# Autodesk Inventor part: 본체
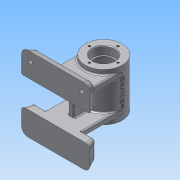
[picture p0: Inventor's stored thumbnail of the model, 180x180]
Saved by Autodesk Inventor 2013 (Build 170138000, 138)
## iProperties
Created: 2016-07
Part Number: 본체
Material: 알루미늄 6061
Document SubType Name: Modeling
Designer: Administrator
Density: 2.71 g/cm^3
Mass: 504.06 g
Surface Area: 540.608 cm^2
Volume: 186 cm^3
Author: Administrator
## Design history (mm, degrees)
sketch "스케치1"
  geometry: C1 r 27 at (0, 0); 1 further point
  constraints: 1 centre point, 1 coincident
  dimensions: "d0" = 54 diameter of C1
extrude "돌출1" new body sketch "스케치1" distance "d1" = 35; taper "d2" = 0 deg
sketch "스케치2"
  geometry: C1 r 27 at (0, 0) reference; C2 r 16 at (0, 0)
  constraints: 1 centre point, 1 coincident
  dimensions: "d3" = 32 diameter of C2
extrude "돌출2" cut sketch "스케치2" distance "d4" = 12; taper "d5" = 0 deg
chamfer "모따기1" distance "d6" = 1; stored, may be unused: second distance "d7" = 2, angle "d8" = 45 deg
fillet "모깎기1" dims "d9" = 0.3
sketch "스케치3"
  geometry: C1 r 15.7 at (0, 0) reference; C2 r 14 at (0, 0)
  constraints: 1 centre point, 1 coincident
  dimensions: "d10" = 28 diameter of C2
extrude "돌출3" cut sketch "스케치3" distance "d11" = 2; taper "d12" = 0 deg
sketch "스케치4"
  geometry: C1 r 27 at (0, 0) reference; C2 r 22 at (0, 0)
  constraints: 1 centre point, 1 coincident
  dimensions: "d13" = 44 diameter of C2
extrude "돌출4" cut sketch "스케치4" distance "d14" = 21; taper "d15" = 0 deg
fillet "모깎기2" dims "d16" = 3
sketch "스케치5"
  geometry: C1 r 27 at (0, 0) reference; 1 further point
  constraints: 1 vertical alignment
  dimensions: "d17" = 21 distance of C1.centre point (0, 21)
hole "구멍1" sketch "스케치5" at (0, 21) diameter "d18" = 3.242; stored, may be unused: countersink angle "d22" = 90 deg, drill point angle "d24" = 118 deg; dims "d19" = 8, "d20" = 4, "d21" = 2, "d23" = 10
node "작업 평면1"
sketch "스케치6"
  geometry: L1 (27, 35)-(-27, 35) reference; C1 r 5 at (0, 13); 2 further points
  constraints: 1 centre point, 1 midpoint, 1 vertical alignment
  dimensions: "d29" = 10 diameter of C1; "d30" = 22 distance from line of C1.centre L1
extrude "돌출5" join sketch "스케치6" stored distance "d31" = 21; taper "d32" = 0 deg
fillet "모깎기3" dims "d33" = 2
sketch "스케치7"
  geometry: C1 r 5 at (0, 0) reference; 2 further points
  constraints: 1 coincident
hole "구멍2" sketch "스케치7" at (0, 0) diameter "d34" = 5.188; stored, may be unused: countersink angle "d38" = 90 deg, drill point angle "d40" = 118 deg; dims "d35" = 8, "d36" = 4, "d37" = 2, "d39" = 10
node "작업 평면2"
sketch "스케치8"
  geometry: L1 (50, 20)-(-50, 20); L2 (-50, 20)-(-50, 55); L3 (-50, 55)-(50, 55); L4 (50, 55)-(50, 20); L5 (50, 20)-(-50, 55); L6 (-50, 20)-(50, 55); 3 further points
  constraints: 12 end point, 3 midpoint, 2 parallel, 1 horizontal, 1 perpendicular, 1 vertical alignment
  dimensions: "d42" = 100 distance of L2.end L3.end; "d43" = 35 distance of L1.end L2.end; "d44" = 55 vertical distance of L2.end point (0, 0)
extrude "돌출6" join sketch "스케치8" distance "d45" = 12; taper "d46" = 0 deg
sketch "스케치12"
  geometry: L1 (50, -20)-(-50, -20) reference; L2 (-50, -55)-(-50, -20) reference; L3 (-50, -20)-(50, -20) reference; L4 (50, -20)-(50, -55) reference; L5 (-27, -20)-(27, -20); L6 (27, -20)-(27, -28); L7 (27, -28)-(-27, -28); L8 (-27, -28)-(-27, -20); L9 (-27, -20)-(27, -28); L10 (27, -20)-(-27, -28); L11 (50, -55)-(-50, -55) reference; 3 further points
  constraints: 12 end point, 4 midpoint, 2 parallel, 1 horizontal, 1 perpendicular
  dimensions: "d65" = 54 distance of L6.end L7.end; "d66" = 8 distance of L5.end L6.end
extrude "돌출8" join sketch "스케치12" stored distance "d67" = 12; taper "d68" = 0 deg
fillet "모깎기6" dims "d69" = 2
fillet "모깎기9" dims "d72" = 2
node "작업 평면3"
sketch "스케치19"
  geometry: L1 (-57.621, 20)-(-70, 20) reference; L2 (-70, 20)-(-70, 55) reference; L3 (-58, 55)-(-58, 29.464) reference; L4 (-56, 26)-(-56, 22) reference; L5 (-56, 26)-(0, 26) reference; L6 (0, 26)-(0, 35) reference; L7 (-56, 22)-(0, 22) reference; L8 (0, -35)-(0, 22) reference; L9 (0, 22)-(0, 26) reference; L10 (27, 35)-(-27, 35) reference; L11 (-70, 55)-(-58, 55) reference; 2 further points
  constraints: 1 coincident, 3 other
  dimensions: "d130" = 35 distance from line of L10 point (0, 0); "d188" = 27 horizontal distance of L10.start point (0, 0) (derived)
feature "엠보싱1" sketch "스케치19" dims "d131" = 0.5, "d132" = 0
node "작업 평면4"
sketch "스케치21"
  geometry: C1 r 6 at (0, 0); 1 further point
  constraints: 1 centre point, 1 coincident
  dimensions: "d136" = 12 diameter of C1
extrude "돌출11" join sketch "스케치21" stored distance "d137" = 12; taper "d138" = 0 deg
fillet "모깎기18" dims "d139" = 2
sketch "스케치22"
  geometry: C1 r 6 at (0, 0) reference; 1 further point
  constraints: 1 coincident
hole "구멍6" sketch "스케치22" at (0, 0) diameter "d140" = 5.134; stored, may be unused: countersink angle "d144" = 90 deg, drill point angle "d146" = 0 deg; dims "d141" = 6, "d142" = 10, "d143" = 4, "d145" = 10
fillet "모깎기23" dims "d171" = 2
sketch "스케치26"
  geometry: L1 (16, 23.3)-(16, 34) reference; L2 (16, 34)-(17, 35) reference; L3 (17, 35)-(19.379, 35) reference; L4 (19.379, 35)-(19.379, 25) reference; L5 (19.379, 25)-(21, 24.026) reference; L6 (21, 24.026)-(22.621, 25) reference; L7 (22.621, 25)-(22.621, 35) reference; L8 (22.621, 35)-(27, 35) reference; L9 (27, 35)-(27, 20) reference; L10 (29, 18)-(30, 18) reference; L11 (30, 18)-(30, 15.594) reference; L12 (30, 15.594)-(22, 15.594) reference; L13 (22, 15.594)-(22, 18) reference; L14 (19, 21)-(14, 21) reference; L15 (14, 21)-(14, 23) reference; L16 (14, 23)-(15.7, 23) reference; L17 (15.7, -23)-(14, -23) reference; L18 (14, -23)-(14, -21) reference; L19 (14, -21)-(19, -21) reference; L20 (22, -18)-(22, 10.406) reference; L21 (22, 10.406)-(30, 10.406) reference; L22 (30, 10.406)-(30, 8) reference; L23 (30, 8)-(29, 8) reference; L24 (27, 6)-(27, -35) reference; L25 (27, -35)-(22.621, -35) reference; L26 (22.621, -35)-(22.621, -25) reference; L27 (22.621, -25)-(21, -24.026) reference; L28 (21, -24.026)-(19.379, -25) reference; L29 (19.379, -25)-(19.379, -35) reference; L30 (19.379, -35)-(17, -35) reference; L31 (17, -35)-(16, -34) reference; L32 (16, -34)-(16, -23.3) reference; L33 (-16, -23.3)-(-16, -34) reference; L34 (-16, -34)-(-17, -35) reference; L35 (-17, -35)-(-19.379, -35) reference; L36 (-19.379, -35)-(-19.379, -25) reference; L37 (-19.379, -25)-(-21, -24.026) reference; L38 (-21, -24.026)-(-22.621, -25) reference; L39 (-22.621, -25)-(-22.621, -35) reference; L40 (-22.621, -35)-(-27, -35) reference; L41 (-27, -35)-(-27, -28) reference; L42 (-58, -55)-(-70, -55) reference; L43 (-70, -55)-(-70, -20) reference; L44 (-70, -20)-(-27, -20) reference; L45 (-27, -20)-(-27, 18) reference; L46 (-29, 20)-(-70, 20) reference; L47 (-70, 20)-(-70, 55) reference; L48 (-70, 55)-(-58, 55) reference; L49 (-58, 55)-(-58, 30) reference; L50 (-56, 28)-(-29, 28) reference; L51 (-27, 30)-(-27, 35) reference; L52 (-27, 35)-(-22.621, 35) reference; L53 (-22.621, 35)-(-22.621, 25) reference; L54 (-22.621, 25)-(-21, 24.026) reference; L55 (-21, 24.026)-(-19.379, 25) reference; L56 (-19.379, 25)-(-19.379, 35) reference; L57 (-19.379, 35)-(-17, 35) reference; L58 (-17, 35)-(-16, 34) reference; L59 (-16, 34)-(-16, 23.3) reference; L60 (-15.7, 23)-(-14, 23) reference; L61 (-14, 23)-(-14, 21) reference; L62 (-14, 21)-(-19, 21) reference; L63 (-22, 18)-(-22, -18) reference; L64 (-19, -21)-(-14, -21) reference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; A1 r 3 centre (19, 18) between (22, 18) and (19, 21) reference; A2 r 0.3 centre (15.7, 23.3) between (15.7, 23) and (16, 23.3) reference; A3 r 0.3 centre (15.7, -23.3) between (16, -23.3) and (15.7, -23) reference; A4 r 3 centre (19, -18) between (19, -21) and (22, -18) reference; A5 r 0.3 centre (-15.7, -23.3) between (-15.7, -23) and (-16, -23.3) reference; A6 r 2 centre (-29, 18) between (-27, 18) and (-29, 20) reference; A7 r 2 centre (-56, 30) between (-58, 30) and (-56, 28) reference; A8 r 2 centre (-29, 30) between (-29, 28) and (-27, 30) reference; A9 r 0.3 centre (-15.7, 23.3) between (-16, 23.3) and (-15.7, 23) reference; A10 r 3 centre (-19, 18) between (-19, 21) and (-22, 18) reference; A11 r 3 centre (-19, -18) between (-22, -18) and (-19, -21) reference; 1 further point
  constraints: 2 end point, 1 perpendicular, 2 other
  dimensions: "d173" = 21 horizontal distance of L67.start L51.end
feature "리브3" sketch "스케치26" dims "d174" = 1, "d175" = 8, "d176" = 0, "d177" = 0, "d178" = 1, "d179" = 1
fillet "모깎기25" dims "d187" = 2
fillet "모깎기27" dims "d190" = 2
sketch "스케치32"
  geometry: L1 (35, 0)-(0, 0) reference; L2 (35, 10)-(35, 0) reference; L3 (35, 0)-(0, 0) reference; L4 (0, 0)-(0, 12) reference; L5 (0, 12)-(33, 12) reference; L6 (75, 0)-(75, 12) reference; L7 (75, 12)-(110, 12) reference; L8 (110, 12)-(110, 0) reference; L9 (110, 0)-(75, 0) reference; L10 (35, 10)-(35, 0) reference; L11 (35, 0)-(0, 0) reference; L12 (0, 0)-(0, 12) reference; L13 (0, 12)-(33, 12) reference; L14 (75, 0)-(75, 12) reference; L15 (75, 12)-(110, 12) reference; L16 (110, 12)-(110, 0) reference; L17 (110, 0)-(75, 0) reference; L18 (110, 0)-(105.632, 12); L19 (0, 0)-(4.368, 12); A1 r 2 centre (33, 10) between (35, 10) and (33, 12) reference; A2 r 2 centre (33, 10) between (35, 10) and (33, 12) reference; 1 further point
  constraints: 4 end point, 2 point on line
  dimensions: "d212" = 110 deg angle of L9 L18; "d214" = 110 deg angle of L1 L19
extrude "돌출16" cut sketch "스케치32" stored distance "d215" = 40; taper "d216" = 0 deg
node "작업 평면5"
sketch "스케치33"
  geometry: L1 (-100, 0)-(-100, 12) reference; L2 (0, 12)-(0, 0) reference; L3 (0, 0)-(-4.368, 12); L4 (-100, 0)-(0, 0) reference; L5 (-100, 12)-(0, 12) reference; L6 (-100, 0)-(-95.632, 12); 1 further point
  constraints: 4 end point, 2 point on line
  dimensions: "d219" = 110 deg angle of L4 L3; "d221" = 110 deg angle of L4 L6
extrude "돌출17" cut sketch "스케치33" distance "d222" = 40; taper "d223" = 0 deg
fillet "모깎기28" dims "d224" = 10
fillet "모깎기29" dims "d225" = 5
fillet "모깎기30" dims "d226" = 2
node "작업 평면6"
sketch "스케치34"
  geometry: L1 (-100, 12)-(0, 12) reference; L2 (0, 0)-(-100, 0) reference; L3 (-100, 0)-(-95.632, 12); L4 (0, 0)-(-4.368, 12); L5 (-100, 0)-(-100, 12) reference; L6 (0, 12)-(0, 0) reference; 1 further point
  constraints: 4 end point, 2 point on line
  dimensions: "d228" = 110 deg angle of L2 L4; "d229" = 110 deg angle of L2 L3
extrude "돌출18" cut sketch "스케치34" distance "d230" = 40; taper "d231" = 0 deg
sketch "스케치35"
  geometry: L1 (-21.83, -52)-(-21.83, -72.433) reference; L2 (-0.536, -50)-(50.536, -50) reference; L3 (67.131, -52)-(54, -52) reference; L4 (67.131, -72.433)-(67.131, -52) reference; L5 (-12.433, -77.131)-(62.433, -77.131) reference; L6 (-17.131, -52)-(-17.131, -72.433) reference; L7 (-4, -52)-(-17.131, -52) reference; L8 (-4, -52)-(-4, -56) reference; L9 (0, -60)-(50, -60) reference; L10 (54, -56)-(54, -52) reference; L11 (-4, -8)-(-4, -4) reference; L12 (0, 0)-(50, 0) reference; L13 (54, -4)-(54, -8) reference; L14 (50, -10)-(0, -10) reference; L15 (-20.632, -8)-(-4, -8) reference; L16 (-20.632, -8)-(-20.632, 20.632) reference; L17 (-20.632, 20.632)-(70.632, 20.632) reference; L18 (70.632, 20.632)-(70.632, -8) reference; L19 (54, -8)-(70.632, -8) reference; L20 (75, -75.603)-(75, -52) reference; L21 (-25, -52)-(-25, -75.603) reference; L22 (-15.603, -85)-(65.603, -85) reference; A1 r 4 centre (0, -56) between (-4, -56) and (0, -60) reference; A2 r 4 centre (50, -56) between (50, -60) and (54, -56) reference; A3 r 4 centre (0, -4) between (0, 0) and (-4, -4) reference; A4 r 4 centre (50, -4) between (54, -4) and (50, 0) reference; A5 r 2 centre (50, -8) between (50, -10) and (51, -9.732) reference; A6 r 2 centre (0, -8) between (-1, -9.732) and (0, -10) reference; 3 further points
  constraints: 1 horizontal alignment, 6 other
  dimensions: "d235" = 12.5 distance from line of L20 point (62.5, -72.5); "d236" = 12.5 distance from line of L21 point (-12.5, -72.5); "d237" = 12.5 distance from line of L22 point (-12.5, -72.5)
hole "구멍9" sketch "스케치35" at (-12.5, -72.5), (62.5, -72.5) diameter "d238" = 6; stored, may be unused: countersink angle "d242" = 90 deg, drill point angle "d244" = 0 deg; dims "d239" = 6, "d240" = 10, "d241" = 4, "d243" = 10
fillet "모깎기31" dims "d245" = 10
fillet "모깎기32" dims "d246" = 5
node "솔리드1"
pattern_circular "원형 패턴1" dims angle "d26" = 360 deg
mirror "대칭1"
mirror "대칭6"
mirror "대칭7"
node "절단 모서리 투영1"
node "절단 모서리 투영5"
node "절단 모서리 투영9"
node "절단 모서리 투영13"
node "절단 모서리 투영14"
node "절단 모서리 투영15"
other parameters: "d129" = 27, "d217" = -35, "d227" = -35
